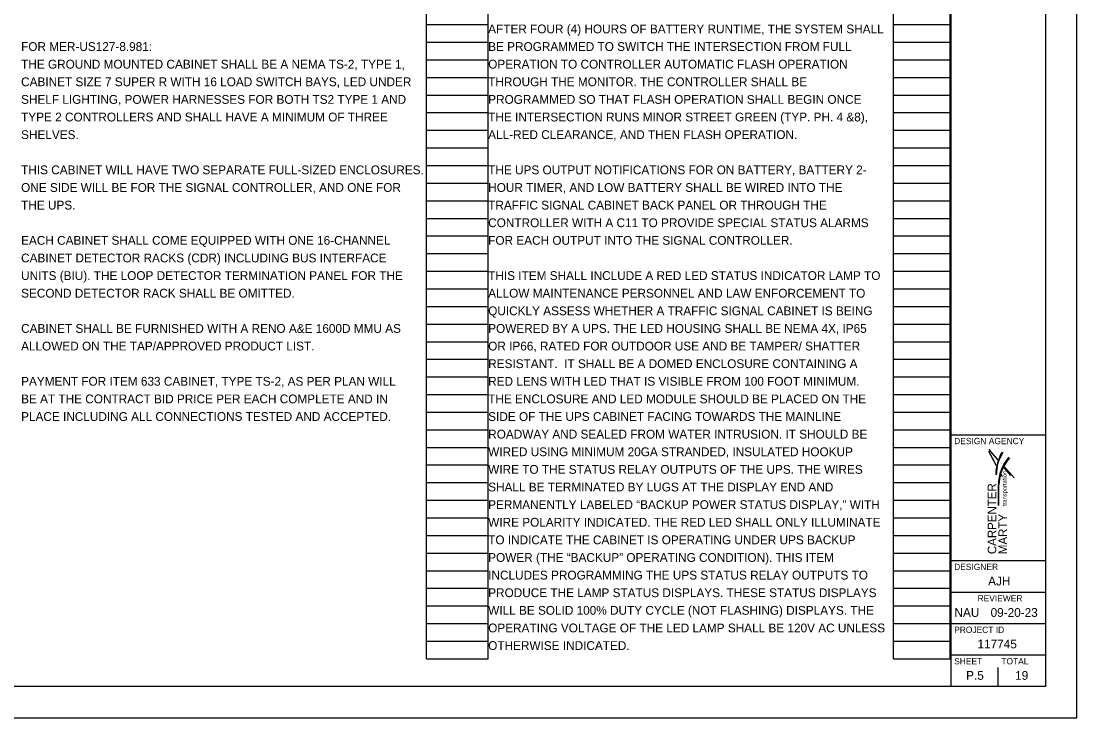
# Model space of a CAD drawing. Extents: x 0 to 34, y -2.4 to 22.
# Drawn here: x 17.24 to 34.01, y 0.04 to 11.11 of the extents above; entities that cross this region are included whole.
import ezdxf

# ---------------------------------------------------------------- set-up
doc = ezdxf.new("R2010")
doc.units = 0
for name, color, linetype in [('SH_Border', 7, 'Continuous'), ('SH_Cut_Line', 7, 'Continuous'), ('SH_Data', 7, 'Continuous'), ('SH_Text', 7, 'Continuous')]:
    doc.layers.add(name, color=color, linetype=linetype)

msp = doc.modelspace()

# ---------------------------------------------------------------- linework, layer by layer
at = {"layer": 'SH_Border'}
for p, q in [((32.012, 0.541), (32.012, 21.541)), ((32.012, 4.541), (33.512, 4.541)), ((32.012, 2.541), (33.512, 2.541)), ((32.012, 2.041), (33.512, 2.041)), ((32.012, 1.541), (33.512, 1.541)), ((32.012, 1.041), (33.512, 1.041))]:
    msp.add_line(p, q, dxfattribs=at)
msp.add_lwpolyline([(1.512, 21.541), (33.512, 21.541), (33.512, 0.541), (1.512, 0.541)], close=True, dxfattribs=at)
at = {"layer": 'SH_Cut_Line'}
msp.add_lwpolyline([(0.012, 0.041), (34.012, 0.041), (34.012, 22.041), (0.012, 22.041)], close=True, dxfattribs=at)
at = {"layer": 'SH_Data'}
for p, q in [((23.68, 0.98), (23.68, 21.14)), ((24.66, 0.98), (24.66, 21.14)), ((31.1, 0.98), (31.1, 21.14)), ((32, 0.98), (32, 21.14)), ((23.68, 11.06), (24.66, 11.06)), ((31.1, 11.06), (32, 11.06)), ((23.68, 10.78), (24.66, 10.78)), ((31.1, 10.78), (32, 10.78)), ((23.68, 10.5), (24.66, 10.5)), ((31.1, 10.5), (32, 10.5)), ((23.68, 10.22), (24.66, 10.22)), ((31.1, 10.22), (32, 10.22)), ((23.68, 9.94), (24.66, 9.94)), ((31.1, 9.94), (32, 9.94)), ((23.68, 9.66), (24.66, 9.66)), ((31.1, 9.66), (32, 9.66)), ((23.68, 9.38), (24.66, 9.38)), ((31.1, 9.38), (32, 9.38)), ((23.68, 9.1), (24.66, 9.1)), ((31.1, 9.1), (32, 9.1)), ((23.68, 8.82), (24.66, 8.82)), ((31.1, 8.82), (32, 8.82)), ((23.68, 8.54), (24.66, 8.54)), ((31.1, 8.54), (32, 8.54)), ((23.68, 8.26), (24.66, 8.26)), ((31.1, 8.26), (32, 8.26)), ((23.68, 7.98), (24.66, 7.98)), ((31.1, 7.98), (32, 7.98)), ((23.68, 7.7), (24.66, 7.7)), ((31.1, 7.7), (32, 7.7)), ((23.68, 7.42), (24.66, 7.42)), ((31.1, 7.42), (32, 7.42)), ((23.68, 7.14), (24.66, 7.14)), ((31.1, 7.14), (32, 7.14)), ((23.68, 6.86), (24.66, 6.86)), ((31.1, 6.86), (32, 6.86)), ((23.68, 6.58), (24.66, 6.58)), ((31.1, 6.58), (32, 6.58)), ((23.68, 6.3), (24.66, 6.3)), ((31.1, 6.3), (32, 6.3)), ((23.68, 6.02), (24.66, 6.02)), ((31.1, 6.02), (32, 6.02)), ((23.68, 5.74), (24.66, 5.74)), ((31.1, 5.74), (32, 5.74)), ((23.68, 5.46), (24.66, 5.46)), ((31.1, 5.46), (32, 5.46)), ((23.68, 5.18), (24.66, 5.18)), ((31.1, 5.18), (32, 5.18)), ((23.68, 4.9), (24.66, 4.9)), ((31.1, 4.9), (32, 4.9)), ((23.68, 4.62), (24.66, 4.62)), ((31.1, 4.62), (32, 4.62)), ((23.68, 4.34), (24.66, 4.34)), ((31.1, 4.34), (32, 4.34)), ((23.68, 4.06), (24.66, 4.06)), ((31.1, 4.06), (32, 4.06)), ((23.68, 3.78), (24.66, 3.78)), ((31.1, 3.78), (32, 3.78)), ((32.762, 3.541), (32.762, 3.541)), ((23.68, 3.5), (24.66, 3.5)), ((31.1, 3.5), (32, 3.5)), ((23.68, 3.22), (24.66, 3.22)), ((31.1, 3.22), (32, 3.22)), ((23.68, 2.94), (24.66, 2.94)), ((31.1, 2.94), (32, 2.94)), ((23.68, 2.66), (24.66, 2.66)), ((31.1, 2.66), (32, 2.66)), ((23.68, 2.38), (24.66, 2.38)), ((31.1, 2.38), (32, 2.38)), ((23.68, 2.1), (24.66, 2.1)), ((31.1, 2.1), (32, 2.1)), ((23.68, 1.82), (24.66, 1.82)), ((31.1, 1.82), (32, 1.82)), ((23.68, 1.54), (24.66, 1.54)), ((31.1, 1.54), (32, 1.54)), ((23.68, 1.26), (24.66, 1.26)), ((31.1, 1.26), (32, 1.26)), ((23.68, 0.98), (24.66, 0.98)), ((31.1, 0.98), (32, 0.98)), ((32.762, 0.541), (32.762, 0.841)), ((32.387, 0.716), (32.387, 0.716))]:
    msp.add_line(p, q, dxfattribs=at)
at = {"layer": 'SH_Text'}
for p, q in [((32.732, 4.057), (32.613, 4.273)), ((32.963, 3.894), (32.846, 4.032)), ((32.851, 4.043), (33.018, 3.857)), ((32.823, 3.881), (32.801, 3.921)), ((32.832, 3.874), (32.803, 3.927)), ((32.767, 3.418), (32.767, 3.745)), ((32.773, 3.418), (32.773, 3.745))]:
    msp.add_line(p, q, dxfattribs=at)
for points in [[(32.758, 4.145), (32.613, 4.307)], [(32.613, 4.307), (32.756, 4.139)], [(32.732, 4.057), (32.613, 4.273)], [(32.613, 4.273), (32.731, 4.052)]]:
    msp.add_lwpolyline(points, dxfattribs=at)
for centre, radius, start, end in [((33.444, 3.901), 0.721, 149.5704, 179.5529), ((33.385, 3.902), 0.654, 147.1423, 179.6525), ((33.437, 3.745), 0.671, 139.2898, 180.0106), ((33.445, 3.729), 0.672, 138.5126, 178.6075)]:
    msp.add_arc(centre, radius, start, end, dxfattribs=at)

# ---------------------------------------------------------------- texts
at = {"layer": 'SH_Data'}
for s, height, p in [('DESIGN AGENCY', 0.1, (32.062, 4.391)), ('DESIGNER', 0.1, (32.062, 2.391)), ('AJH', 0.14, (32.602, 2.146)), ('REVIEWER', 0.1, (32.434, 1.891)), ('NAU', 0.14, (32.067, 1.646)), ('09-20-23', 0.14, (32.641, 1.646)), ('PROJECT ID', 0.1, (32.062, 1.391)), ('117745', 0.14, (32.433, 1.146)), ('SHEET', 0.1, (32.062, 0.891)), ('TOTAL', 0.1, (32.812, 0.891)), ('P.5', 0.14, (32.252, 0.646)), ('19', 0.14, (33.031, 0.646))]:
    msp.add_text(s, height=height, dxfattribs=at).set_placement(p)
at = {"layer": 'SH_Text'}
for s, p in [('AFTER FOUR (4) HOURS OF BATTERY RUNTIME, THE SYSTEM SHALL ', (24.66, 10.92)), ('FOR MER-US127-8.981:', (17.24, 10.64)), ('BE PROGRAMMED TO SWITCH THE INTERSECTION FROM FULL ', (24.66, 10.64)), ('THE GROUND MOUNTED CABINET SHALL BE A NEMA TS-2, TYPE 1, ', (17.24, 10.36)), ('OPERATION TO CONTROLLER AUTOMATIC FLASH OPERATION ', (24.66, 10.36)), ('CABINET SIZE 7 SUPER R WITH 16 LOAD SWITCH BAYS, LED UNDER ', (17.24, 10.08)), ('THROUGH THE MONITOR. THE CONTROLLER SHALL BE ', (24.66, 10.08)), ('SHELF LIGHTING, POWER HARNESSES FOR BOTH TS2 TYPE 1 AND ', (17.24, 9.8)), ('PROGRAMMED SO THAT FLASH OPERATION SHALL BEGIN ONCE ', (24.66, 9.8)), ('TYPE 2 CONTROLLERS AND SHALL HAVE A MINIMUM OF THREE ', (17.24, 9.52)), ('THE INTERSECTION RUNS MINOR STREET GREEN (TYP. PH. 4 &8), ', (24.66, 9.52)), ('SHELVES.', (17.24, 9.24)), ('ALL-RED CLEARANCE, AND THEN FLASH OPERATION. ', (24.66, 9.24)), ('THIS CABINET WILL HAVE TWO SEPARATE FULL-SIZED ENCLOSURES. ', (17.24, 8.68)), ('THE UPS OUTPUT NOTIFICATIONS FOR ON BATTERY, BATTERY 2-', (24.66, 8.68)), ('ONE SIDE WILL BE FOR THE SIGNAL CONTROLLER, AND ONE FOR ', (17.24, 8.4)), ('HOUR TIMER, AND LOW BATTERY SHALL BE WIRED INTO THE ', (24.66, 8.4)), ('THE UPS. ', (17.24, 8.12)), ('TRAFFIC SIGNAL CABINET BACK PANEL OR THROUGH THE ', (24.66, 8.12)), ('CONTROLLER WITH A C11 TO PROVIDE SPECIAL STATUS ALARMS ', (24.66, 7.84)), ('EACH CABINET SHALL COME EQUIPPED WITH ONE 16-CHANNEL ', (17.24, 7.56)), ('FOR EACH OUTPUT INTO THE SIGNAL CONTROLLER. ', (24.66, 7.56)), ('CABINET DETECTOR RACKS (CDR) INCLUDING BUS INTERFACE ', (17.24, 7.28)), ('UNITS (BIU). THE LOOP DETECTOR TERMINATION PANEL FOR THE ', (17.24, 7)), ('THIS ITEM SHALL INCLUDE A RED LED STATUS INDICATOR LAMP TO ', (24.66, 7)), ('SECOND DETECTOR RACK SHALL BE OMITTED.', (17.24, 6.72)), ('ALLOW MAINTENANCE PERSONNEL AND LAW ENFORCEMENT TO ', (24.66, 6.72)), ('QUICKLY ASSESS WHETHER A TRAFFIC SIGNAL CABINET IS BEING ', (24.66, 6.44)), ('CABINET SHALL BE FURNISHED WITH A RENO A&E 1600D MMU AS ', (17.24, 6.16)), ('POWERED BY A UPS. THE LED HOUSING SHALL BE NEMA 4X, IP65 ', (24.66, 6.16)), ('ALLOWED ON THE TAP/APPROVED PRODUCT LIST. ', (17.24, 5.88)), ('OR IP66, RATED FOR OUTDOOR USE AND BE TAMPER/ SHATTER ', (24.66, 5.88)), ('RESISTANT.  IT SHALL BE A DOMED ENCLOSURE CONTAINING A ', (24.66, 5.6)), ('PAYMENT FOR ITEM 633 CABINET, TYPE TS-2, AS PER PLAN WILL', (17.24, 5.32)), ('RED LENS WITH LED THAT IS VISIBLE FROM 100 FOOT MINIMUM. ', (24.66, 5.32)), ('BE AT THE CONTRACT BID PRICE PER EACH COMPLETE AND IN', (17.24, 5.04)), ('THE ENCLOSURE AND LED MODULE SHOULD BE PLACED ON THE ', (24.66, 5.04)), ('PLACE INCLUDING ALL CONNECTIONS TESTED AND ACCEPTED.', (17.24, 4.76)), ('SIDE OF THE UPS CABINET FACING TOWARDS THE MAINLINE ', (24.66, 4.76)), ('ROADWAY AND SEALED FROM WATER INTRUSION. IT SHOULD BE ', (24.66, 4.48)), ('WIRED USING MINIMUM 20GA STRANDED, INSULATED HOOKUP ', (24.66, 4.2)), ('WIRE TO THE STATUS RELAY OUTPUTS OF THE UPS. THE WIRES ', (24.66, 3.92)), ('SHALL BE TERMINATED BY LUGS AT THE DISPLAY END AND ', (24.66, 3.64)), ('PERMANENTLY LABELED “BACKUP POWER STATUS DISPLAY,” WITH ', (24.66, 3.36)), ('WIRE POLARITY INDICATED. THE RED LED SHALL ONLY ILLUMINATE ', (24.66, 3.08)), ('TO INDICATE THE CABINET IS OPERATING UNDER UPS BACKUP ', (24.66, 2.8)), ('POWER (THE “BACKUP” OPERATING CONDITION). THIS ITEM ', (24.66, 2.52)), ('INCLUDES PROGRAMMING THE UPS STATUS RELAY OUTPUTS TO ', (24.66, 2.24)), ('PRODUCE THE LAMP STATUS DISPLAYS. THESE STATUS DISPLAYS ', (24.66, 1.96)), ('WILL BE SOLID 100% DUTY CYCLE (NOT FLASHING) DISPLAYS. THE ', (24.66, 1.68)), ('OPERATING VOLTAGE OF THE LED LAMP SHALL BE 120V AC UNLESS ', (24.66, 1.4)), ('OTHERWISE INDICATED.', (24.66, 1.12))]:
    msp.add_text(s, height=0.14, dxfattribs=at).set_placement(p)
for s, height, p in [('transportation', 0.06649, (32.897, 3.405)), ('CARPENTER ', 0.1367, (32.731, 2.643)), ('MARTY', 0.1367, (32.902, 2.643))]:
    msp.add_text(s, height=height, rotation=90, dxfattribs=at).set_placement(p)

doc.saveas('drawing.dxf')
